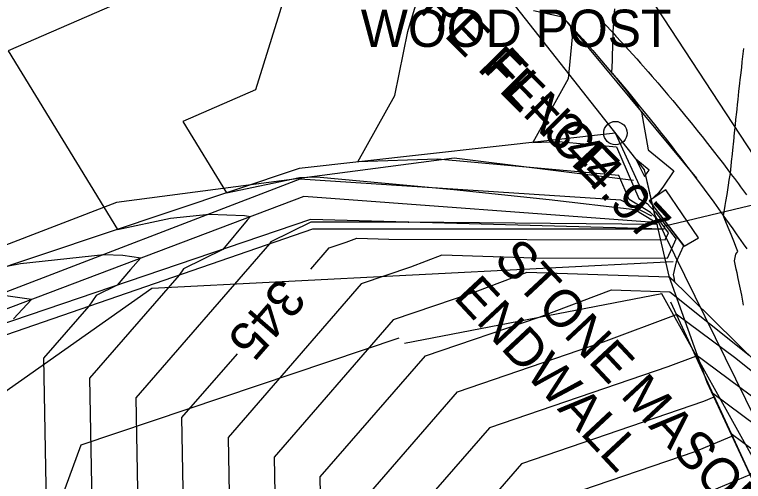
# Model space of a CAD drawing. Extents: x 487096 to 489566, y 221939 to 224454.
# Drawn here: x 488339.9 to 488402.4, y 223512.7 to 223552.7 of the extents above; entities that cross this region are included whole.
import ezdxf

# ---------------------------------------------------------------- set-up
doc = ezdxf.new("R2010")
doc.units = 0
for name, color, linetype in [('SV_BKLN_BKLN', 7, 'Continuous'), ('SV_BKLN_EARTH_TOP', 7, 'Continuous'), ('SV_DRAN_DRAN_TX', 7, 'Continuous'), ('SV_DRAN_END_WALL', 7, 'Continuous'), ('SV_FENC_FENCES', 7, 'Continuous'), ('SV_FENC_FENCES_TX', 7, 'Continuous'), ('SV_PIPE_RC_15', 7, 'Continuous'), ('SV_ROAD_BITRD', 7, 'Continuous'), ('SV_ROWL_HWYLOC', 7, 'Continuous'), ('SV_SIGN_SIGN_', 7, 'Continuous'), ('SV_SIGN_SIGN_TX', 7, 'Continuous'), ('SV_SURF_INDEX_CONTOUR', 7, 'Continuous'), ('SV_SURF_INTER_CONTOUR', 7, 'Continuous'), ('SV_TRAF_PVMTL', 7, 'Continuous'), ('SV_TREE_TREELN', 7, 'Continuous'), ('SV_TREE_TREEVEG', 7, 'Continuous'), ('SV_UTOH_OVERHEAD_LINES', 7, 'Continuous'), ('SV_WATR_INWETF', 7, 'Continuous'), ('SV_WATR_STREAM', 7, 'Continuous')]:
    doc.layers.add(name, color=color, linetype=linetype)

msp = doc.modelspace()

# ---------------------------------------------------------------- linework, layer by layer
at = {"layer": 'SV_BKLN_BKLN'}
for points in [[(488386.936, 223552.434), (488398.354, 223538.659)], [(488394.736, 223534.864), (488364.695, 223537.11), (488337.646, 223526.862), (488336.998, 223527.313)], [(488395.978, 223530.274), (488413.334, 223513.157)]]:
    msp.add_lwpolyline(points, dxfattribs=at)
at = {"layer": 'SV_BKLN_EARTH_TOP'}
for points in [[(488393.957, 223536.983), (488391.408, 223542.535), (488364.309, 223539.493), (488336.74, 223530.251), (488330.512, 223531.301), (488313.833, 223516.625)], [(488395.576, 223534.306), (488365.441, 223534.307), (488338.376, 223524.957), (488337.452, 223525.096)], [(488396.133, 223528.066), (488405.176, 223508.394), (488413.006, 223498.439), (488419.528, 223486.959), (488427.323, 223441.182)]]:
    msp.add_lwpolyline(points, dxfattribs=at)
at = {"layer": 'SV_DRAN_END_WALL'}
msp.add_lwpolyline([(488395.725, 223537.661), (488394.312, 223536.717), (488397.3, 223532.824), (488398.513, 223533.554), (488395.725, 223537.661)], dxfattribs=at)
at = {"layer": 'SV_FENC_FENCES'}
msp.add_lwpolyline([(488362.041, 223571.419), (488379.111, 223558.17), (488393.88, 223539.376), (488395.978, 223530.274), (488399.247, 223521.174), (488405.176, 223508.394), (488413.006, 223498.439), (488427.323, 223441.182)], dxfattribs=at)
at = {"layer": 'SV_PIPE_RC_15'}
msp.add_lwpolyline([(488444.216, 223546.186), (488395.526, 223534.518)], dxfattribs=at)
at = {"layer": 'SV_ROAD_BITRD'}
msp.add_lwpolyline([(488386.524, 223552.911), (488386.965, 223552.426), (488387.624, 223551.696), (488388.278, 223550.962), (488388.603, 223550.595), (488389.18, 223549.939), (488389.467, 223549.61), (488389.896, 223549.116), (488390.536, 223548.372), (488391.172, 223547.625), (488391.488, 223547.25), (488392.118, 223546.498), (488392.431, 223546.121), (488392.899, 223545.555), (488393.451, 223544.88), (488393.726, 223544.542), (488394.137, 223544.034), (488394.75, 223543.27), (488395.358, 223542.502), (488395.661, 223542.117), (488396.264, 223541.344), (488396.564, 223540.957), (488397.011, 223540.374), (488397.605, 223539.594), (488397.9, 223539.203), (488398.342, 223538.615), (488398.999, 223537.73), (488399.827, 223536.6), (488400.238, 223536.033), (488400.85, 223535.179), (488401.457, 223534.321), (488401.76, 223533.891), (488402.36, 223533.028), (488402.659, 223532.596)], dxfattribs=at)
at = {"layer": 'SV_ROWL_HWYLOC'}
msp.add_lwpolyline([(488362.041, 223571.419), (488379.111, 223558.17), (488393.88, 223539.376), (488394.741, 223535.644), (488413.006, 223498.439), (488420.164, 223469.81), (488427.323, 223441.182), (488428.59, 223411.485), (488428.888, 223402.557), (488428.648, 223363.443), (488428.288, 223340.613), (488424.744, 223306.137), (488415.388, 223241.145), (488415.007, 223209.78)], dxfattribs=at)
at = {"layer": 'SV_SIGN_SIGN_'}
msp.add_circle((488391.408, 223542.535), 1, dxfattribs=at)
at = {"layer": 'SV_SURF_INDEX_CONTOUR'}
for points in [[(488365.305, 223530.87), (488366.882, 223532.688), (488368.332, 223533.184), (488369.257, 223533.531), (488371.98, 223533.443), (488395.667, 223533.393), (488395.943, 223533.99), (488395.957, 223533.994), (488395.314, 223534.837), (488394.497, 223535.637), (488394.42, 223535.727), (488392.579, 223536.847), (488391.699, 223538.885), (488376.16, 223540.303), (488369.329, 223540.057), (488372.505, 223545.764), (488373.627, 223551.25), (488376.523, 223561.035), (488374.698, 223563.283)], [(488351.49, 223439.384), (488352.434, 223448.561), (488355.477, 223462.981), (488354.745, 223494.856), (488354.675, 223495.028), (488354.26, 223518.135), (488359.015, 223523.618)], [(488415.584, 223510.692), (488412.717, 223512.796), (488398.182, 223523.608), (488398.256, 223523.367), (488395.89, 223522.479), (488380.62, 223517.26), (488374.461, 223510.159)]]:
    msp.add_lwpolyline(points, dxfattribs=at)
at = {"layer": 'SV_SURF_INTER_CONTOUR'}
for points in [[(488366.205, 223564.349), (488360.573, 223546.251), (488354.34, 223543.522), (488358.094, 223537.409), (488364.345, 223538.734), (488365.794, 223538.786), (488377.569, 223537.711), (488385.727, 223536.852), (488393.06, 223535.981), (488394.684, 223535.009), (488395.015, 223534.684), (488373.65, 223534.896), (488373.697, 223534.894), (488365.313, 223534.908), (488361.885, 223533.211), (488361.759, 223533.035), (488350.309, 223519.833), (488350.762, 223494.521)], [(488354.959, 223556.405), (488339.361, 223549.576), (488348.754, 223534.279), (488353.282, 223535.238), (488356.591, 223535.591), (488359.637, 223535.46), (488360.145, 223535.386), (488359.847, 223535.06), (488357.755, 223532.565), (488354.405, 223530.907), (488354.015, 223530.36), (488346.357, 223521.53), (488346.85, 223494.014)], [(488384.394, 223553.037), (488386.878, 223552.501), (488386.94, 223552.433), (488387.021, 223552.343), (488387.089, 223552.266), (488387.12, 223552.231), (488387.169, 223552.174), (488387.192, 223552.148), (488387.223, 223552.112), (488387.265, 223552.063), (488387.302, 223552.018), (488387.319, 223551.998), (488387.35, 223551.96), (488387.364, 223551.943), (488387.383, 223551.918), (488387.405, 223551.891), (488387.415, 223551.878), (488387.428, 223551.859), (488387.448, 223551.834), (488387.465, 223551.81), (488387.473, 223551.799), (488387.488, 223551.778), (488387.494, 223551.768), (488387.504, 223551.754), (488387.521, 223551.728), (488387.689, 223550.767), (488387.369, 223547.189), (488384.338, 223541.741), (488386.525, 223541.82), (488391.501, 223541.366), (488393.418, 223536.93), (488394.138, 223536.492), (488394.404, 223536.18), (488394.81, 223535.782), (488396.602, 223533.432), (488396.595, 223533.43), (488395.829, 223531.773), (488384.444, 223531.797), (488376.531, 223532.052), (488373.844, 223531.043), (488369.63, 223529.603), (488358.212, 223516.438), (488358.587, 223495.536)], [(488391.33, 223553.177), (488391.286, 223552.548), (488391.278, 223552.468), (488391.189, 223551.232), (488391.188, 223551.222), (488391.183, 223551.146), (488391.175, 223550.69), (488391.171, 223550.552), (488391.158, 223549.909), (488391.134, 223549.252), (488391.119, 223548.734), (488391.074, 223547.74), (488391.136, 223547.665), (488391.329, 223547.431), (488391.683, 223546.997), (488391.845, 223546.795), (488392.071, 223546.51), (488392.315, 223546.197), (488392.429, 223546.05), (488392.589, 223545.84), (488392.809, 223545.545), (488393.007, 223545.274), (488393.098, 223545.147), (488393.268, 223544.906), (488393.346, 223544.792), (488393.456, 223544.629), (488393.648, 223544.336), (488394.215, 223541.103), (488396.417, 223539.286), (488395.46, 223537.906), (488395.09, 223537.418), (488394.386, 223536.767), (488394.672, 223536.247), (488397.247, 223532.869), (488397.247, 223532.869), (488396.61, 223531.493), (488396.369, 223530.366), (488396.38, 223530.316), (488396.385, 223530.293), (488396.393, 223530.26), (488396.402, 223530.215), (488396.409, 223530.178), (488396.413, 223530.161), (488396.417, 223530.136), (488396.423, 223530.102), (488396.429, 223530.07), (488396.431, 223530.055), (488396.435, 223530.031), (488396.436, 223530.019), (488396.439, 223530.002), (488396.442, 223529.978), (488396.445, 223529.955), (488396.446, 223529.945), (488396.457, 223529.803), (488395.985, 223530.181), (488383.806, 223530.573), (488379.355, 223528.902), (488372.377, 223526.517), (488362.164, 223514.741), (488362.499, 223496.043)], [(488402.38, 223527.792), (488402.292, 223528.286), (488402.226, 223528.64), (488402.178, 223528.888), (488402.074, 223529.416), (488401.939, 223530.067), (488401.837, 223530.54), (488401.764, 223530.874), (488401.602, 223531.593), (488401.722, 223532.154), (488401.894, 223532.369), (488401.724, 223532.812), (488401.598, 223533.133), (488401.315, 223533.845), (488401.154, 223534.242), (488400.788, 223535.136), (488400.659, 223535.445), (488400.812, 223536.32), (488400.871, 223536.675), (488400.971, 223537.269), (488401.004, 223537.475), (488401.098, 223538.066), (488401.167, 223538.491), (488401.235, 223538.939), (488401.258, 223539.095), (488401.388, 223540.358), (488401.404, 223540.481), (488401.49, 223541.352), (488401.519, 223541.579), (488401.574, 223542.132), (488401.593, 223542.284), (488401.688, 223543.27), (488401.74, 223543.687), (488401.801, 223544.341), (488401.833, 223544.596), (488401.869, 223544.988), (488401.924, 223545.428), (488401.986, 223546.114), (488402.072, 223546.81), (488402.098, 223547.102), (488402.146, 223547.499), (488402.227, 223548.174), (488402.268, 223548.633), (488402.405, 223549.795)], [(488339.415, 223531.148), (488340.423, 223531.361), (488347.577, 223532.124), (488349.2, 223532.054), (488350.756, 223531.828), (488349.843, 223530.829), (488348.721, 223529.491), (488346.926, 223528.603), (488346.272, 223527.685), (488342.405, 223523.227), (488342.938, 223493.507)], [(488366.411, 223496.55), (488366.115, 223513.044), (488375.125, 223523.431), (488384.867, 223526.761), (488391.08, 223529.094), (488396.072, 223528.933), (488402.86, 223523.487)], [(488339.839, 223526.598), (488341.366, 223528.271), (488338.763, 223528.649)], [(488370.067, 223511.347), (488377.872, 223520.346), (488390.378, 223524.62), (488396.63, 223526.967), (488396.612, 223527.023), (488401.716, 223523.227), (488409.264, 223517.171)], [(488411.024, 223511.808), (488399.752, 223520.193), (488399.85, 223519.875), (488398.961, 223519.504), (488383.367, 223514.175), (488377.971, 223507.952)], [(488386.115, 223511.089), (488398.229, 223515.229), (488401.392, 223516.552), (488401.322, 223516.777), (488409.332, 223510.82)], [(488407.639, 223509.832), (488402.892, 223513.362), (488402.933, 223513.229), (488397.497, 223510.954)]]:
    msp.add_lwpolyline(points, dxfattribs=at)
msp.add_lwpolyline([(488394.301, 223539.361), (488393.146, 223540.313), (488393.898, 223538.81), (488394.142, 223539.132)], close=True, dxfattribs=at)
at = {"layer": 'SV_TRAF_PVMTL'}
msp.add_lwpolyline([(488389.511, 223552.922), (488390.198, 223552.198), (488390.54, 223551.835), (488391.145, 223551.187), (488391.446, 223550.861), (488391.896, 223550.372), (488392.565, 223549.635), (488393.23, 223548.894), (488393.561, 223548.522), (488394.218, 223547.775), (488394.545, 223547.4), (488395.033, 223546.835), (488395.607, 223546.164), (488395.893, 223545.826), (488396.319, 223545.319), (488396.955, 223544.555), (488397.585, 223543.787), (488397.899, 223543.402), (488398.522, 223542.628), (488398.831, 223542.239), (488399.293, 223541.654), (488399.904, 223540.871), (488400.208, 223540.477), (488400.661, 223539.885), (488401.335, 223538.993), (488401.598, 223538.643), (488401.945, 223538.174), (488402.119, 223537.939), (488402.636, 223537.232)], dxfattribs=at)
at = {"layer": 'SV_TREE_TREELN'}
msp.add_lwpolyline([(488372.848, 223524.962), (488345.591, 223515.782), (488315.545, 223433.799)], dxfattribs=at)
at = {"layer": 'SV_TREE_TREEVEG'}
msp.add_lwpolyline([(488469.572, 222626.729), (488414.357, 222775.799), (488391.306, 222875.646), (488384.757, 223013.776), (488396.275, 223079.007), (488413.65, 223210.141), (488414.482, 223247.549), (488427.956, 223341.619), (488424.883, 223443.612), (488411.442, 223499.763), (488395.395, 223528.757), (488373.339, 223524.504)], dxfattribs=at)
at = {"layer": 'SV_UTOH_OVERHEAD_LINES'}
msp.add_lwpolyline([(488477.012, 222631.438), (488424.125, 222778.25), (488391.68, 223012.955), (488449.873, 223205.72), (488469.995, 223438.334), (488349.561, 223622.886), (488159.178, 223693.118), (487993.175, 223755.783), (487804.196, 223830.216), (487742.262, 223860.212)], dxfattribs=at)
at = {"layer": 'SV_WATR_INWETF'}
for points in [[(488392.951, 223538.467), (488377.591, 223540.374), (488348.653, 223536.588), (488322.282, 223526.421), (488300.731, 223488.93), (488278.082, 223417.696)], [(488318.074, 223481.951), (488317.38, 223505.041), (488351.676, 223529.226), (488396.355, 223531.52)]]:
    msp.add_lwpolyline(points, dxfattribs=at)
at = {"layer": 'SV_WATR_STREAM'}
for points in [[(488394.535, 223535.417), (488391.866, 223536.777), (488364.352, 223538.575), (488337.288, 223528.167), (488336.137, 223528.357)], [(488395.596, 223534.309), (488365.268, 223535.121), (488338.282, 223525.94), (488337.216, 223525.176)]]:
    msp.add_lwpolyline(points, dxfattribs=at)

# ---------------------------------------------------------------- texts
at = {"layer": 'SV_DRAN_DRAN_TX'}
for s, p in [('FL=344.97', (488379.991, 223547.98)), ('STONE MASONRY', (488380.879, 223531.62)), ('ENDWALL', (488377.443, 223528.412))]:
    msp.add_text(s, height=3.2, rotation=313.03859, dxfattribs=at).set_placement(p)
at = {"layer": 'SV_FENC_FENCES_TX'}
msp.add_text('BARBED WIRE FENCE', height=3.2, rotation=314.81757, dxfattribs=at).set_placement((488357.542, 223570.117))
at = {"layer": 'SV_SIGN_SIGN_TX'}
msp.add_text('WOOD POST', height=3.2, dxfattribs=at).set_placement((488369.588, 223549.924))
at = {"layer": 'SV_SURF_INDEX_CONTOUR'}
msp.add_text('345', height=3.2, rotation=229.064, dxfattribs=at).set_placement((488362.688, 223530.295))

doc.saveas('drawing.dxf')
